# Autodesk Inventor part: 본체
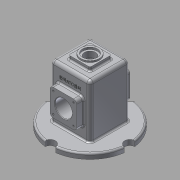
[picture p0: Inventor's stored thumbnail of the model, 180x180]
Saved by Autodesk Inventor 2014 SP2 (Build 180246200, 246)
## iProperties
Created: 2018-07
Part Number: 본체
Material: 알루미늄 6061
Document SubType Name: Modeling
Designer: 거성
Density: 2.71 g/cm^3
Appearance: 알루미늄 - 평지
Mass: 923.617 g
Surface Area: 1023.38 cm^2
Volume: 340.818 cm^3
Author: 거성
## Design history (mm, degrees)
sketch "스케치1"
  geometry: L1 (-37, 37)-(37, 37); L2 (37, 37)-(37, -37); L3 (37, -37)-(-37, -37); L4 (-37, -37)-(-37, 37); 3 further points
  constraints: 8 end point, 2 midpoint, 2 parallel, 1 horizontal, 1 horizontal alignment, 1 perpendicular, 1 vertical alignment
  dimensions: "d0" = 74 distance of L1.start L1.end; "d1" = 74 distance of L1.end L2.end
extrude "돌출1" new body sketch "스케치1" distance "d2" = 110; taper "d3" = 0 deg
feature "쉘1" dims "d4" = 5
node "작업 평면1"
sketch "스케치2"
  geometry: L1 (-20, 20)-(20, 20); L2 (20, 20)-(20, -20); L3 (20, -20)-(-20, -20); L4 (-20, -20)-(-20, 20); 3 further points
  constraints: 8 end point, 2 midpoint, 2 parallel, 1 horizontal, 1 horizontal alignment, 1 perpendicular, 1 vertical alignment
  dimensions: "d6" = 40 distance of L1.start L1.end; "d7" = 40 distance of L1.end L2.end
extrude "돌출2" join sketch "스케치2" stored distance "d8" = 10; taper "d9" = 0 deg
sketch "스케치3"
  geometry: C1 r 17.5 at (0, 0); 1 further point
  constraints: 1 centre point, 1 coincident
  dimensions: "d10" = 35 diameter of C1
extrude "돌출3" join sketch "스케치3" distance "d11" = 3; taper "d12" = 0 deg
hole "구멍1" diameter "d15" = 21; stored, may be unused: countersink angle "d19" = 90 deg, drill point angle "d21" = 0 deg; dims "d13" = 10, "d14" = 10, "d16" = 6, "d17" = 28, "d18" = 4, "d20" = 20
sketch "스케치4"
  geometry: L1 (37, 37)-(-37, 37) reference; L2 (32, -32)-(32, 32) reference; L3 (32, 32)-(-32, 32) reference; L4 (-32, 32)-(-32, -32) reference; L5 (-32, -32)-(32, -32) reference; L6 (37, 37)-(37, -37) reference; L7 (37, -37)-(-37, -37) reference; L8 (-37, -37)-(-37, 37) reference; L9 (-37, 37)-(37, 37) reference; C1 r 75 at (0, 0); 1 further point
  constraints: 1 centre point, 1 coincident
  dimensions: "d22" = 150 diameter of C1
extrude "돌출4" join sketch "스케치4" distance "d23" = 10; taper "d24" = 0 deg
sketch "스케치5"
  geometry: L1 (0, 74)-(100, 74) reference; L2 (30, 62)-(80, 62); L3 (80, 62)-(80, 12); L4 (80, 12)-(30, 12); L5 (30, 12)-(30, 62); L6 (110, 112)-(110, -38) reference; 1 further point
  constraints: 8 end point, 2 parallel, 1 horizontal, 1 perpendicular
  dimensions: "d25" = 50 distance of L2.start L2.end; "d26" = 50 distance of L4.end L2.start; "d27" = 30 distance between parallel lines of L3 L6; "d28" = 12 distance between parallel lines of L2 L1
extrude "돌출5" join sketch "스케치5" distance "d29" = 13; taper "d30" = 0 deg
sketch "스케치6"
  geometry: L1 (-105, 0)-(-105, 64) reference; L2 (5, 69)-(-95, 69) reference; C1 r 25 at (-50, 32); 1 further point
  constraints: 1 centre point
  dimensions: "d31" = 55 distance from line of C1.centre L1; "d32" = 37 distance from line of C1.centre L2; "d33" = 50 diameter of C1
extrude "돌출6" join sketch "스케치6" distance "d34" = 7; taper "d35" = -20 deg
sketch "스케치7"
  geometry: C1 r 25 at (55, 37) reference; C2 r 16 at (55, 37); 1 further point
  constraints: 1 centre point, 1 coincident
  dimensions: "d36" = 32 diameter of C2
extrude "돌출7" cut sketch "스케치7" stored distance "d37" = 7; taper "d38" = 0 deg
sketch "스케치8"
  geometry: L1 (37, 37)-(-37, 37) reference; L2 (0, 2.478)-(0, 75); C1 r 10 at (0, 75); 1 further point
  constraints: 2 end point, 2 vertical alignment, 1 centre point, 1 coincident, 1 perpendicular, 1 other
  dimensions: "d39" = 20 diameter of C1
extrude "돌출8" cut sketch "스케치8" stored distance "d40" = 7; taper "d41" = 0 deg
sketch "스케치9"
  geometry: L1 (80, 62)-(30, 62) reference; L2 (30, 62)-(30, 12) reference; L3 (30, 12)-(80, 12) reference; L4 (80, 12)-(80, 62) reference; 5 further points
  constraints: 2 horizontal alignment, 2 vertical alignment
  dimensions: "d45" = 6 distance from line of point (36, 56) L1; "d46" = 6 distance from line of L2 point (36, 56); "d47" = 6 distance from line of L3 point (36, 18); "d48" = 6 distance from line of L4 point (74, 56)
hole "구멍2" sketch "스케치9" at (36, 56), (74, 56), (74, 18), (36, 18) diameter "d49" = 3.242; stored, may be unused: countersink angle "d53" = 90 deg, drill point angle "d55" = 118 deg; dims "d50" = 8, "d51" = 28, "d52" = 4, "d54" = 10
fillet "모깎기1" dims "d56" = 6
fillet "모깎기2" dims "d57" = 3
fillet "모깎기3" dims "d58" = 6
fillet "모깎기4" dims "d59" = 3
fillet "모깎기5" dims "d60" = 3
sketch "스케치10"
  geometry: L1 (16, 13.5)-(16, 48.5) reference; 2 further points
  constraints: 1 horizontal alignment, 1 other
  dimensions: "d61" = 30 distance from line of L1 point (-14, 31)
feature "엠보싱1" sketch "스케치10" dims "d0" = 74, "d1" = 74, "d62" = 0.5, "d63" = 0
chamfer "모따기1" distance "d64" = 1; stored, may be unused: second distance "d65" = 2, angle "d66" = 45 deg
node "솔리드1"
mirror "대칭1"
pattern_circular "원형 패턴1" dims angle "d43" = 360 deg
mirror "대칭2"
node "절단 모서리 투영1"
other parameters: "d5" = -117
